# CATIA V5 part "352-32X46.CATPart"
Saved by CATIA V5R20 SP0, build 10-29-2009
Part number: 352-32X46
Definition: NONE
Nomenclature: 352-32X46
Source: Unknown
Description: 352-32X46
Bounding box of the stored display mesh (mm): x 0 to 46, y -20 to 20, z -20 to 20
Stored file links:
  C:\Users\Utente\Desktop\IO LAVORO\3D X SITO CF\X SITO\PLASTICA\352\352-32X46.CATPart
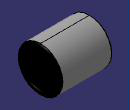
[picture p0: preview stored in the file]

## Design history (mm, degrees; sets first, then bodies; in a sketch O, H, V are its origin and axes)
Body1 "352-32X46" (main body)
  Solid1: solid without history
